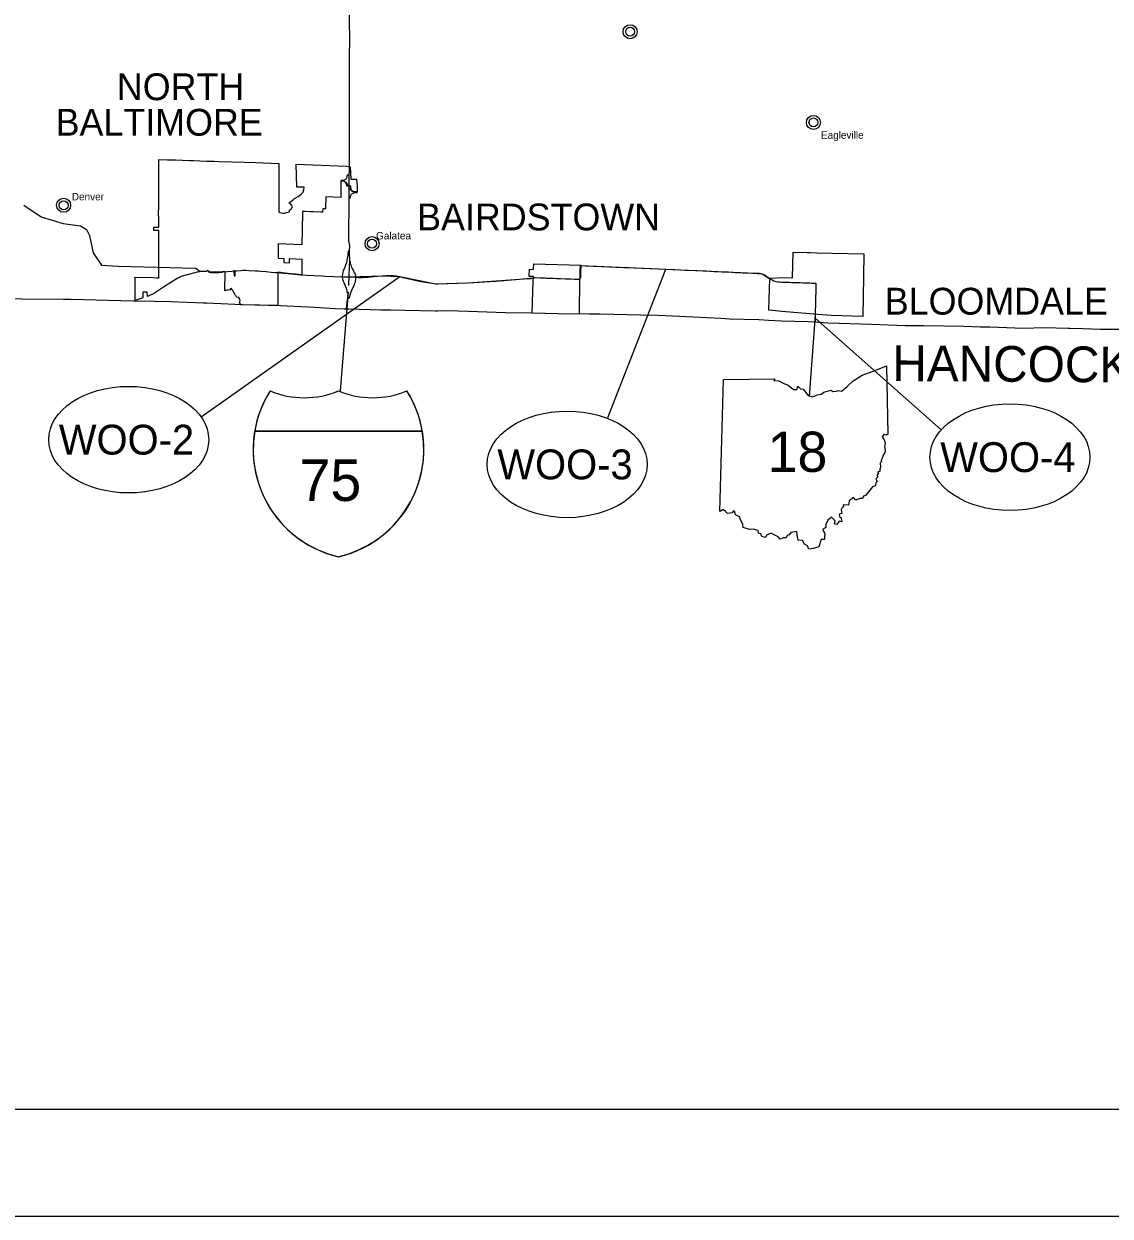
# Model space of a CAD drawing. Extents: x 0 to 851, y 0 to 440.
# Drawn here: x 282.5 to 384.3, y 0 to 111.8 of the extents above; entities that cross this region are included whole.
import ezdxf

# ---------------------------------------------------------------- set-up
doc = ezdxf.new("R2010")
doc.units = 0
for name, color, linetype in [('DV_X_Corp_Line', 7, 'Continuous'), ('GM_X_Adjacent_County_Text', 7, 'Continuous'), ('GM_X_Corporation_Text', 7, 'Continuous'), ('GM_X_County', 7, 'Continuous'), ('GM_X_Interstate_Route', 7, 'Continuous'), ('GM_X_State_Route', 7, 'Continuous'), ('PV_P_Text', 7, 'Continuous'), ('RD_P_Fence', 7, 'Continuous'), ('SH_Border', 7, 'Continuous'), ('SH_Cut_Line', 7, 'Continuous'), ('SH_Data', 7, 'Continuous')]:
    doc.layers.add(name, color=color, linetype=linetype)

msp = doc.modelspace()

# ---------------------------------------------------------------- linework, layer by layer
at = {"layer": 'DV_X_Corp_Line'}
for points in [[(306.86, 89.42), (307.38, 89.4), (307.39, 89.8), (308.54, 89.74), (308.53, 88.29), (306.94, 88.45), (306.54, 88.49), (306.3, 88.52), (306.29, 85.39), (302.86, 85.48), (302.69, 85.64), (302.73, 85.74), (302.74, 85.87), (302.73, 85.99), (302.63, 86.15), (302.45, 86.18), (302.41, 86.22), (302.37, 86.28), (302.33, 86.35), (302.26, 86.48), (302.14, 86.69), (302.04, 86.86), (301.99, 86.86), (301.91, 86.99), (301.8, 86.98), (301.8, 86.83), (301.62, 86.86), (301.33, 86.79), (301.35, 88.58), (301.05, 88.56), (300.85, 88.54), (300.6, 88.53), (300.26, 88.53), (300.09, 88.53), (299.99, 88.54), (299.92, 88.55), (299.85, 88.58), (299.79, 88.61), (299.7, 88.68), (299.59, 88.59), (299.58, 88.58), (299.55, 88.58), (299.52, 88.58), (299.13, 88.59), (299.03, 88.58), (298.96, 88.58), (298.91, 88.57), (298.86, 88.56), (297.3, 88.16), (297.21, 88.12), (297.16, 88.1), (296.84, 87.92), (296.35, 87.62), (295.57, 87.13), (295.09, 86.8), (294.8, 86.61), (294.62, 86.49), (294.48, 86.42), (294.25, 86.33), (294.05, 86.26), (294.04, 86.64), (293.63, 86.64), (293.63, 86.11), (293.37, 86.02), (292.92, 85.86), (292.9, 88.06), (294.59, 88.02), (294.91, 88.01), (295.03, 88.01), (295.1, 88.01), (295.15, 88.02), (295.14, 88.05), (295.14, 88.08), (295.13, 88.16), (295.13, 88.22), (295.12, 89.6), (295.12, 89.86), (295.13, 90.13), (295.12, 90.68), (295.13, 92.45), (294.67, 92.45), (294.67, 92.74), (295.12, 92.74), (295.12, 93.53), (295.11, 94.06), (295.12, 94.66), (295.12, 97.51), (295.12, 99.11), (295.93, 99.07), (296.7, 99.05), (297.35, 99.03), (298.02, 99), (298.39, 98.99), (298.96, 98.97), (299.63, 98.95), (300.32, 98.93), (300.71, 98.92), (301.96, 98.89), (303.14, 98.85), (304.19, 98.82), (306.38, 98.72), (306.37, 94.16), (306.48, 94.13), (306.61, 94.1), (306.78, 94.07), (306.91, 94.07), (307.08, 94.11), (307.37, 94.19), (307.39, 94.34), (307.45, 94.37), (307.47, 94.36), (307.48, 94.4), (307.54, 94.44), (307.66, 94.65), (307.61, 94.78), (307.52, 94.9), (307.32, 95.02), (307.4, 95.08), (307.51, 95.16), (307.74, 95.35), (307.84, 95.43), (307.96, 95.49), (308.2, 95.64), (308.32, 95.72), (308.52, 95.87), (308.59, 95.96), (308.65, 96.04), (308.72, 96.24), (308.76, 96.51), (308.07, 96.5), (308.02, 98.65), (312.72, 98.47), (313.07, 98.41), (313.13, 97.24), (313.66, 97.25), (313.69, 96.86), (313.72, 96.63), (313.72, 96.45), (313.72, 96.36), (313.72, 96.3), (313.72, 96.2), (313.72, 96.15), (313.72, 96.05), (313.49, 96.05), (313.44, 96.05), (313.41, 96.06), (313.38, 96.07), (313.34, 96.09), (313.31, 96.11), (313.28, 96.13), (313.26, 96.15), (313.23, 96.17), (313.22, 96.19), (313.19, 96.22), (313.18, 96.25), (313.16, 96.3), (313.15, 96.33), (313.14, 96.37), (313.14, 96.41), (313.14, 96.46), (313.14, 96.5), (313.14, 96.58), (313.06, 96.59), (312.76, 96.6), (312.73, 96.82), (312.67, 96.9), (312.6, 96.98), (312.5, 97.03), (312.43, 97.05), (312.35, 97.07), (312.19, 97.07), (312.18, 96.76), (312.18, 95.52), (310.79, 95.6), (310.75, 94.46), (310.49, 94.47), (310.48, 94.14), (310.32, 94.14), (309.62, 94.18), (309.35, 94.19), (308.86, 94.21), (308.59, 94.22), (308.59, 94.06), (308.54, 91.1), (306.33, 91.17), (306.33, 90.96), (306.32, 90.06), (306.32, 89.84), (306.85, 89.82)], [(352.33, 84.97), (352.42, 87.98), (353.78, 88.03), (354.56, 87.99), (354.62, 90.41), (355.92, 90.38), (356.21, 90.37), (356.84, 90.35), (361.24, 90.26), (361.21, 88.08), (361.14, 84.38), (358.16, 84.48), (356.91, 84.57), (353.56, 84.85)], [(302.17, 88.64), (302.18, 88.19), (302.28, 88.19), (302.27, 88.65)], [(330.15, 84.67), (330.24, 87.72), (330.25, 87.99), (330.25, 88.12), (329.85, 88.13), (329.87, 88.8), (330.27, 88.78), (330.27, 88.88), (330.29, 89.32), (334.71, 89.17), (334.68, 88.5), (334.68, 88.17), (334.68, 88.11), (334.67, 88.07), (334.66, 88.01), (334.64, 87.99), (334.63, 87.96), (334.61, 87.94), (334.59, 87.92), (334.57, 87.91), (334.54, 84.59), (332.57, 84.62)]]:
    msp.add_lwpolyline(points, close=True, dxfattribs=at)
for centre, radius in [((339.32, 111.08), 0.658), ((339.32, 111.08), 0.417), ((356.51, 102.57), 0.658), ((356.51, 102.57), 0.417), ((286.2, 94.8), 0.658), ((286.2, 94.8), 0.417), ((315.12, 91.2), 0.658), ((315.12, 91.2), 0.417)]:
    msp.add_circle(centre, radius, dxfattribs=at)
at = {"layer": 'GM_X_County'}
msp.add_lwpolyline([(387, 83.16), (383.38, 83.14), (381.79, 83.21), (380.55, 83.24), (380.36, 83.24), (378.22, 83.31), (376.19, 83.25), (373.04, 83.36), (372.17, 83.38), (370.6, 83.42), (366.84, 83.48), (365.44, 83.49), (365.1, 83.5), (361.95, 83.62), (357.87, 83.76), (356.62, 83.85), (356.03, 83.86), (353.52, 83.92), (352.29, 84), (351.38, 84.07), (348.64, 84.13), (347.84, 84.18), (343.99, 84.38), (341.91, 84.47), (340.29, 84.49), (339, 84.53), (336.51, 84.6), (335.52, 84.58), (332.57, 84.62), (330.16, 84.67), (330.13, 84.67), (327.64, 84.73), (324.14, 84.83), (323.19, 84.87), (322.04, 84.89), (321.26, 84.88), (321.06, 84.87), (316.85, 84.96), (315.99, 84.98), (312.94, 85.05), (312.92, 85.05), (312.7, 85.06), (312.51, 85.06), (311.66, 85.08), (309.72, 85.22), (306.54, 85.36), (302.95, 85.47), (299.61, 85.61), (299.33, 85.62), (296.26, 85.75), (294.7, 85.78), (292.76, 85.82), (286.9, 85.95), (286.18, 85.96), (278.4, 86.02)], dxfattribs=at)
at = {"layer": 'GM_X_Interstate_Route'}
for points in [[(313.01, 102.55), (313.02, 103.1), (313.02, 103.86), (313.02, 104.69), (313.02, 105.49), (313.02, 106.36), (313.02, 107.34), (313.02, 108.27), (313.02, 109.12), (313.03, 109.93), (313.03, 110.81), (313.01, 111.63), (313.01, 113.29)], [(313, 99.37), (313.02, 100.1), (313.01, 100.74), (313.02, 101.42), (313.01, 102.21), (313.01, 102.55), (313.01, 102.55)], [(312.98, 96.63), (312.98, 96.72), (312.99, 97.64), (313, 98.01), (313, 98.32), (313, 98.4)], [(313, 98.4), (313, 98.62), (313, 99.33), (313, 99.37), (313, 99.37)], [(312.95, 91.91), (312.95, 92.34), (312.95, 93.16), (312.96, 93.93), (312.97, 94.52), (312.97, 95.5), (312.98, 95.91), (312.98, 96.18)], [(312.98, 96.18), (312.98, 96.35), (312.98, 96.63)], [(313.01, 89.14), (313.03, 89.5), (313.02, 90.51), (313.03, 91.04), (312.95, 91.48), (312.95, 91.88), (312.95, 91.91)], [(312.97, 88.08), (313.01, 89.14)], [(312.93, 87.28), (312.94, 87.39), (312.97, 88.08)], [(312.7, 85.06), (312.76, 85.33), (312.8, 85.7), (312.84, 86.1), (312.88, 86.66), (312.14, 77.41)]]:
    msp.add_lwpolyline(points, dxfattribs=at)
at = {"layer": 'GM_X_State_Route'}
for points in [[(312.99, 97.64), (312.79, 97.64), (312.79, 97.59), (312.77, 97.5), (312.75, 97.43), (312.72, 97.37), (312.69, 97.3), (312.65, 97.26), (312.61, 97.21), (312.56, 97.18), (312.51, 97.15), (312.45, 97.13), (312.4, 97.11), (312.22, 97.12), (312.2, 97.12)], [(312.19, 97.07), (312.22, 97.07), (312.36, 97.08), (312.46, 97.07), (312.54, 97.04), (312.61, 97.01), (312.66, 96.96), (312.71, 96.92), (312.74, 96.87), (312.78, 96.81), (312.79, 96.74), (312.79, 96.73), (312.98, 96.72)], [(313.77, 96.03), (313.74, 96.03), (313.49, 96.02), (313.43, 96.03), (313.35, 96.05), (313.28, 96.08), (313.23, 96.12), (313.18, 96.17), (313.14, 96.23), (313.11, 96.29), (313.09, 96.35), (313.09, 96.35), (313.03, 96.35), (312.98, 96.35)], [(312.97, 95.5), (313.03, 95.5), (313.08, 95.5), (313.1, 95.59), (313.13, 95.71), (313.17, 95.8), (313.23, 95.86), (313.28, 95.91), (313.34, 95.95), (313.41, 95.97), (313.49, 95.99), (313.74, 95.99), (313.77, 95.99)], [(282.48, 94.8), (284.08, 93.73), (286.14, 93.1), (287.78, 92.87), (288.33, 92.52), (288.61, 91.97), (288.96, 90.33), (289.76, 89.17), (291.3, 89.1), (298.61, 88.9), (298.99, 88.58)], [(313.02, 90.51), (312.87, 90.51), (312.86, 90.26), (312.84, 90.1), (312.81, 89.94), (312.79, 89.78), (312.76, 89.62), (312.71, 89.41), (312.64, 89.19), (312.57, 89), (312.49, 88.85), (312.42, 88.68), (312.37, 88.51), (312.34, 88.36), (312.33, 88.14), (312.33, 88.09)], [(313.6, 88.06), (313.59, 88.1), (313.59, 88.2), (313.57, 88.28), (313.53, 88.4), (313.49, 88.51), (313.27, 88.9), (313.23, 88.97), (313.19, 89.08), (313.14, 89.22), (313.11, 89.36), (313.1, 89.5), (313.03, 89.5)], [(299.75, 88.63), (299.78, 88.59), (299.87, 88.54), (299.99, 88.51), (300.14, 88.5), (300.26, 88.5), (300.44, 88.51), (300.74, 88.51), (301.05, 88.54), (301.05, 88.54)], [(301.05, 88.54), (301.14, 88.55), (301.57, 88.59), (301.99, 88.62), (302.23, 88.64)], [(302.23, 88.64), (302.23, 88.64), (302.42, 88.66), (302.81, 88.7), (302.96, 88.71), (302.96, 88.71)], [(302.96, 88.71), (303.04, 88.72), (303.04, 88.72)], [(303.04, 88.72), (303.1, 88.73), (303.17, 88.73), (303.27, 88.73), (303.58, 88.7), (304.2, 88.65), (304.44, 88.64), (304.44, 88.64)], [(304.44, 88.64), (304.68, 88.62), (305.19, 88.58), (305.67, 88.54), (306.01, 88.51), (306.29, 88.5)], [(306.29, 88.5), (306.81, 88.45)], [(306.81, 88.45), (306.93, 88.44), (306.94, 88.44), (308.48, 88.28)], [(334.54, 87.86), (334.57, 87.88), (334.61, 87.91), (334.63, 87.96), (334.64, 88.16), (334.65, 88.59), (334.68, 89.14)], [(334.68, 89.14), (335.18, 89.12), (335.89, 89.1), (336.66, 89.07), (337.35, 89.04), (338.02, 89.01), (338.72, 88.98), (339.1, 88.97), (339.22, 88.96), (339.87, 88.94), (340.6, 88.91), (341.23, 88.88), (341.3, 88.88), (341.98, 88.85), (342.68, 88.81), (343.36, 88.78), (343.51, 88.77), (343.51, 88.77)], [(343.51, 88.77), (344.08, 88.75), (344.48, 88.73)], [(344.48, 88.73), (344.48, 88.73), (344.8, 88.71), (345.6, 88.67), (346.44, 88.64), (347.21, 88.6), (347.92, 88.57), (348.55, 88.55), (349.18, 88.51), (349.82, 88.48), (350.3, 88.46), (350.31, 88.46)], [(350.31, 88.46), (350.39, 88.46), (351.08, 88.43), (351.45, 88.42), (351.58, 88.4), (351.71, 88.36), (351.83, 88.31), (351.97, 88.24), (352.18, 88.1), (352.38, 87.96), (352.39, 87.95)], [(308.48, 88.28), (308.49, 88.28), (308.51, 88.28), (308.54, 88.28), (308.97, 88.24), (310.41, 88.17)], [(310.41, 88.17), (310.76, 88.15), (312.33, 88.09), (312.97, 88.08)], [(312.33, 88.09), (312.33, 88.04), (312.39, 87.79), (312.69, 87.02), (312.73, 86.91), (312.76, 86.79), (312.77, 86.66), (312.88, 86.66)], [(312.84, 86.1), (312.94, 86.08), (312.99, 86.08), (313.04, 86.24), (313.07, 86.39), (313.14, 86.58), (313.17, 86.67), (313.24, 86.85), (313.48, 87.38), (313.52, 87.49), (313.56, 87.62), (313.58, 87.75), (313.59, 87.82), (313.59, 88.02), (313.6, 88.06)], [(312.97, 88.08), (313.6, 88.06)], [(313.6, 88.06), (313.89, 88.04), (314.19, 88.04), (314.45, 88.05)], [(314.45, 88.05), (314.76, 88.07), (314.98, 88.09), (315.61, 88.14), (316.06, 88.18), (316.07, 88.18)], [(316.07, 88.18), (316.47, 88.21), (316.72, 88.23), (316.91, 88.23), (317.12, 88.21), (317.38, 88.19), (317.72, 88.11), (318.02, 88.04), (318.31, 87.97), (319.4, 87.72), (319.56, 87.68), (319.96, 87.62), (320.9, 87.46), (321.1, 87.44), (321.33, 87.43), (322.23, 87.46), (323.07, 87.5), (324.13, 87.54), (326.74, 87.7), (328.94, 87.86), (329.81, 87.92)], [(329.81, 87.92), (329.92, 87.93), (330.03, 87.94), (330.15, 87.96), (330.24, 88)], [(330.24, 88), (330.34, 88.02), (330.41, 88.03), (330.86, 88.01), (330.92, 88.01), (331.34, 87.99), (331.47, 87.98), (331.67, 87.98), (332.06, 87.96), (332.16, 87.96), (332.41, 87.94), (332.78, 87.93), (332.8, 87.93), (333.26, 87.91), (333.42, 87.9), (333.75, 87.89), (334.1, 87.87), (334.53, 87.86), (334.54, 87.86), (334.54, 87.86)], [(352.39, 87.95), (352.4, 87.95), (352.63, 87.81), (352.79, 87.73), (352.89, 87.69), (353.02, 87.66), (353.17, 87.63), (353.33, 87.61), (353.5, 87.6), (353.67, 87.6), (353.72, 87.6), (353.79, 87.6), (353.82, 87.6)], [(353.82, 87.6), (354.17, 87.58), (354.28, 87.58), (354.5, 87.57), (354.87, 87.56), (355.28, 87.55), (355.51, 87.54), (355.63, 87.54), (356.01, 87.52), (356.16, 87.52), (356.32, 87.51), (356.73, 87.5)], [(356.73, 87.5), (356.72, 86.99), (356.72, 86.88), (356.72, 86.6), (356.71, 86.25), (356.71, 86.16), (356.69, 85.63), (356.69, 85.61), (356.69, 85.25), (356.69, 85.24)], [(356.69, 85.24), (356.68, 85.09), (356.68, 85.07), (356.67, 84.56), (356.67, 84.51), (356.12, 76.87)]]:
    msp.add_lwpolyline(points, dxfattribs=at)
at = {"layer": 'PV_P_Text'}
for p, q in [((347.73, 66.08), (348.07, 78.45)), ((347.73, 66.08), (348.07, 78.45)), ((304.12, 73.63), (319.83, 73.63)), ((319.83, 73.63), (304.12, 73.63)), ((319.83, 73.63), (304.12, 73.63))]:
    msp.add_line(p, q, dxfattribs=at)
for points in [[(348.07, 78.45), (352.88, 78.53), (352.8, 78.38), (353.25, 78.35), (353.73, 78.09), (354.14, 77.92), (354.64, 77.53), (354.94, 77.53), (355.06, 77.85), (355.29, 77.6), (355.56, 77.56), (356.03, 76.97), (356.42, 76.84), (356.88, 77.04), (357.22, 77.08), (357.48, 77.28), (358.14, 77.45), (358.32, 77.35), (358.67, 77.37), (358.84, 77.44), (359.15, 77.37), (359.68, 77.82), (360.23, 78.35), (361.08, 78.86), (362.35, 79.33), (363.35, 79.75), (363.5, 73.33)], [(348.07, 78.45), (352.88, 78.53), (352.8, 78.38), (353.25, 78.35), (353.73, 78.09), (354.14, 77.92), (354.64, 77.53), (354.94, 77.53), (355.06, 77.85), (355.29, 77.6), (355.56, 77.56), (356.03, 76.97), (356.42, 76.84), (356.88, 77.04), (357.22, 77.08), (357.48, 77.28), (358.14, 77.45), (358.32, 77.35), (358.67, 77.37), (358.84, 77.44), (359.15, 77.37), (359.68, 77.82), (360.23, 78.35), (361.08, 78.86), (362.35, 79.33), (363.35, 79.75), (363.5, 73.33)], [(363.5, 73.33), (363.35, 73.24), (363.12, 73.29), (362.96, 73.1), (363.15, 72.8), (363.24, 72.49), (363.16, 72.14), (363.24, 71.85), (363.19, 71.61), (363.04, 71.37), (362.99, 71.14), (362.87, 70.9), (362.88, 70.76), (362.76, 70.65), (362.79, 70.25), (362.73, 70.03), (362.75, 69.84), (362.56, 69.79), (362.6, 69.63), (362.48, 69.51), (362.51, 69.3), (362.37, 69.16), (362.5, 68.89), (362.39, 68.81), (362.31, 68.48), (362.06, 68.41), (361.57, 67.81), (361.4, 67.59), (361.21, 67.53), (361.1, 67.3), (360.86, 67.3), (360.5, 67.14), (360.27, 67.41), (359.86, 67.08), (359.81, 66.69), (359.3, 66.71), (359.32, 66.51), (359.2, 66.45), (359.1, 66.26), (359.16, 65.91), (358.92, 65.82), (358.95, 65.62), (359.1, 65.5), (359.17, 65.11), (358.91, 65.19), (358.7, 64.87), (358.49, 64.94), (358.56, 65.22), (358.19, 65.55), (357.85, 65.28), (357.66, 64.86), (357.66, 64.57), (357.4, 64.4), (357.57, 64), (357.54, 63.72), (357.55, 63.46), (357.22, 63.47), (357.03, 62.76)], [(363.5, 73.33), (363.35, 73.24), (363.12, 73.29), (362.96, 73.1), (363.15, 72.8), (363.24, 72.49), (363.16, 72.14), (363.24, 71.85), (363.19, 71.61), (363.04, 71.37), (362.99, 71.14), (362.87, 70.9), (362.88, 70.76), (362.76, 70.65), (362.79, 70.25), (362.73, 70.03), (362.75, 69.84), (362.56, 69.79), (362.6, 69.63), (362.48, 69.51), (362.51, 69.3), (362.37, 69.16), (362.5, 68.89), (362.39, 68.81), (362.31, 68.48), (362.06, 68.41), (361.57, 67.81), (361.4, 67.59), (361.21, 67.53), (361.1, 67.3), (360.86, 67.3), (360.5, 67.14), (360.27, 67.41), (359.86, 67.08), (359.81, 66.69), (359.3, 66.71), (359.32, 66.51), (359.2, 66.45), (359.1, 66.26), (359.16, 65.91), (358.92, 65.82), (358.95, 65.62), (359.1, 65.5), (359.17, 65.11), (358.91, 65.19), (358.7, 64.87), (358.49, 64.94), (358.56, 65.22), (358.19, 65.55), (357.85, 65.28), (357.66, 64.86), (357.66, 64.57), (357.4, 64.4), (357.57, 64), (357.54, 63.72), (357.55, 63.46), (357.22, 63.47), (357.03, 62.76)], [(357.03, 62.76), (356.47, 62.62), (356.08, 62.54), (355.94, 62.86), (355.66, 63.03), (355.48, 63.36), (355.08, 63.4), (354.99, 63.85), (354.94, 64.21), (354.4, 64.12), (354.25, 63.9), (354.05, 63.84), (353.94, 63.62), (353.68, 63.6), (353.39, 63.49), (353.21, 63.71), (352.75, 63.93), (352.54, 64.05), (352.1, 63.87), (352.01, 63.66), (351.66, 63.75), (351.58, 63.99), (351.37, 64.06), (351.32, 64.3), (350.87, 64.43), (350.53, 64.38), (349.92, 64.58), (349.89, 64.9), (349.68, 65.3), (349.57, 65.57), (349.19, 65.78), (349.11, 66.11), (348.99, 66.1), (348.88, 65.97), (348.45, 65.91), (348.28, 66.04), (348.04, 66.27), (347.73, 66.08)], [(357.03, 62.76), (356.47, 62.62), (356.08, 62.54), (355.94, 62.86), (355.66, 63.03), (355.48, 63.36), (355.08, 63.4), (354.99, 63.85), (354.94, 64.21), (354.4, 64.12), (354.25, 63.9), (354.05, 63.84), (353.94, 63.62), (353.68, 63.6), (353.39, 63.49), (353.21, 63.71), (352.75, 63.93), (352.54, 64.05), (352.1, 63.87), (352.01, 63.66), (351.66, 63.75), (351.58, 63.99), (351.37, 64.06), (351.32, 64.3), (350.87, 64.43), (350.53, 64.38), (349.92, 64.58), (349.89, 64.9), (349.68, 65.3), (349.57, 65.57), (349.19, 65.78), (349.11, 66.11), (348.99, 66.1), (348.88, 65.97), (348.45, 65.91), (348.28, 66.04), (348.04, 66.27), (347.73, 66.08)]]:
    msp.add_lwpolyline(points, dxfattribs=at)
for centre, radius, start, end in [((314.3, 71.9), 10.33, 147.8216, 256.9941), ((313.65, 72.08), 9.66, 146.654, 170.759), ((308.77, 84.99), 8.24, 247.0848, 292.9105), ((308.77, 84.99), 8.24, 247.0848, 292.9105), ((309.65, 71.9), 10.33, 283.0065, 32.1787), ((315.18, 84.99), 8.24, 247.0916, 292.9084), ((315.18, 84.99), 8.24, 247.0916, 292.9084), ((309.65, 71.9), 10.33, 9.6475, 32.179), ((314.3, 71.9), 10.33, 170.3514, 256.9967), ((309.67, 71.9), 10.31, 282.7667, 9.6898)]:
    msp.add_arc(centre, radius, start, end, dxfattribs=at)
at = {"layer": 'RD_P_Fence'}
msp.add_line((356.67, 84.56), (356.67, 83.9), dxfattribs=at)
for points in [[(334.68, 89.14), (342.68, 88.81), (350.39, 88.46), (351.71, 88.36), (352.39, 87.95)], [(312.97, 88.08), (316.07, 88.18), (317.72, 88.11), (321.1, 87.44), (324.13, 87.54), (328.94, 87.86), (330.24, 88)]]:
    msp.add_lwpolyline(points, dxfattribs=at)
at = {"layer": 'SH_Border'}
msp.add_lwpolyline([(30, 430), (670, 430), (670, 10), (30, 10)], close=True, dxfattribs=at)
at = {"layer": 'SH_Cut_Line'}
msp.add_lwpolyline([(0, 0), (680, 0), (680, 440), (0, 440)], close=True, dxfattribs=at)
at = {"layer": 'SH_Data'}
for p, q in [((337.21, 74.81), (342.68, 88.81)), ((299.09, 74.95), (317.72, 88.11)), ((368.49, 73.73), (356.67, 84.23))]:
    msp.add_line(p, q, dxfattribs=at)
for centre in [(292.3, 72.82), (374.94, 71.18), (333.42, 70.5)]:
    msp.add_ellipse(centre, major_axis=(7.5, 0), ratio=0.666667, dxfattribs=at)

# ---------------------------------------------------------------- texts
at = {"layer": 'DV_X_Corp_Line'}
for s, p in [('Eagleville', (357.22, 101.04)), ('Denver', (286.97, 95.26)), ('Galatea', (315.5, 91.6))]:
    msp.add_text(s, height=0.698, rotation=0, dxfattribs=at).set_placement(p)
at = {"layer": 'GM_X_Adjacent_County_Text'}
msp.add_text('HANCOCK COUNTY', height=3.35, rotation=359.6476, dxfattribs=at).set_placement((363.9, 78.32))
at = {"layer": 'GM_X_Corporation_Text'}
for s, p in [('NORTH', (291.19, 104.66)), ('BALTIMORE', (285.45, 101.33)), ('BAIRDSTOWN', (319.35, 92.45)), ('BLOOMDALE', (363.2, 84.55))]:
    msp.add_text(s, height=2.513, rotation=0, dxfattribs=at).set_placement(p)
at = {"layer": 'PV_P_Text'}
for s, height, p in [('18', 3.769, (352.21, 69.8)), ('75', 3.901, (308.31, 67.07))]:
    msp.add_text(s, height=height, dxfattribs=at).set_placement(p)
at = {"layer": 'SH_Data'}
for s, p in [('WOO-2', (285.75, 71.42)), ('WOO-3', (326.87, 69.1)), ('WOO-4', (368.4, 69.78))]:
    msp.add_text(s, height=2.8, dxfattribs=at).set_placement(p)

doc.saveas('drawing.dxf')
